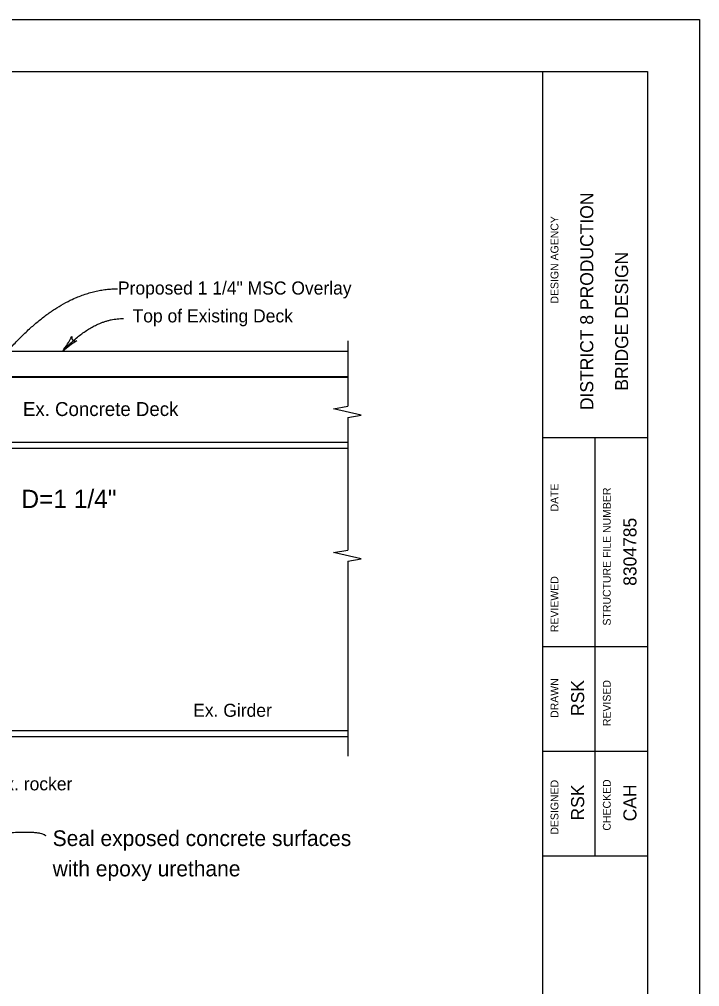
# Model space of a CAD drawing. Extents: x -706 to 14950, y -1867 to 6417.
# Drawn here: x 613.1 to 808.2, y -1354.2 to -1076.7 of the extents above; entities that cross this region are included whole.
import ezdxf

# ---------------------------------------------------------------- set-up
doc = ezdxf.new("R2010")
doc.units = 0
for name, color, linetype in [('Level 1', 7, 'Continuous'), ('Level 42', 7, 'Continuous'), ('Level 43', 7, 'Continuous'), ('Level 44', 7, 'Continuous'), ('Level 47', 7, 'Continuous')]:
    doc.layers.add(name, color=color, linetype=linetype)

msp = doc.modelspace()

# ---------------------------------------------------------------- linework, layer by layer
at = {"layer": 'Level 1'}
for p, q in [((763.17, -1721.66), (763.17, -1091.66)), ((763.17, -1196.66), (793.17, -1196.66)), ((778.17, -1316.66), (778.17, -1196.66)), ((763.17, -1256.66), (793.17, -1256.66)), ((763.17, -1286.66), (793.17, -1286.66)), ((763.17, -1316.66), (793.17, -1316.66))]:
    msp.add_line(p, q, dxfattribs=at)
for points in [[(-211.83, -1076.66), (808.17, -1076.66), (808.17, -1736.66), (-211.83, -1736.66)], [(-151.83, -1091.66), (793.17, -1091.66), (793.17, -1721.66), (-151.83, -1721.66)]]:
    msp.add_lwpolyline(points, close=True, dxfattribs=at)
at = {"layer": 'Level 42'}
for p, q in [((543.75, -1171.85), (707.26, -1171.85)), ((535.62, -1179.35), (707.26, -1179.35))]:
    msp.add_line(p, q, dxfattribs=at)
msp.add_lwpolyline([(543.05, -1179.26), (543.05, -1171.85), (707.26, -1171.85), (707.26, -1179.26)], close=True, dxfattribs=at)
at = {"layer": 'Level 43'}
for p, q in [((536.79, -1198.02), (707.26, -1198.02)), ((536.79, -1199.71), (707.26, -1199.71)), ((531.77, -1280.73), (707.26, -1280.73)), ((531.77, -1282.41), (707.26, -1282.41))]:
    msp.add_line(p, q, dxfattribs=at)
at = {"layer": 'Level 44'}
for p, q in [((629.51, -1168.91), (629.51, -1168.91)), ((707.26, -1168.93), (707.26, -1187.7)), ((703.2, -1188.4), (707.26, -1187.7)), ((711.11, -1190.22), (703.2, -1188.4)), ((707.26, -1190.88), (711.11, -1190.22)), ((707.26, -1190.88), (707.26, -1228.96)), ((703.2, -1229.65), (707.26, -1228.96)), ((711.11, -1231.48), (703.2, -1229.65)), ((707.26, -1232.13), (711.11, -1231.48)), ((707.26, -1232.13), (707.26, -1288.06))]:
    msp.add_line(p, q, dxfattribs=at)
for centre, start, end in [((595.76, -1150.18), 323.9167, 331.6712), ((649.25, -1199.97), 122.437, 130.1914)]:
    msp.add_arc(centre, 36.8, start, end, dxfattribs=at)
msp.add_ellipse((629.27, -1167.8), major_axis=(-0.849, -0.912), ratio=0.873734, start_param=5.258637, end_param=7.300638, dxfattribs=at)
msp.add_open_spline([(597.3, -1313.98), (606.24, -1310.1), (619.74, -1309.68), (620.58, -1310.95)], degree=2, dxfattribs=at)
at = {"layer": 'Level 47'}
for points in [[(608.06, -1173.83), (624.63, -1153.99), (641.2, -1153.99)], [(625.5, -1171.85), (634.21, -1162.5), (642.92, -1162.5)]]:
    msp.add_open_spline(points, degree=2, dxfattribs=at)

# ---------------------------------------------------------------- texts
at = {"layer": 'Level 1'}
for s, height, p in [('  DISTRICT 8 PRODUCTION  ', 3.75, (777.67, -1191.57)), ('DESIGN AGENCY', 2.25, (767.67, -1158.22)), ('      BRIDGE DESIGN      ', 3.75, (787.67, -1191.57)), ('DATE', 2.25, (767.67, -1217.88)), ('STRUCTURE FILE NUMBER', 2.25, (782.67, -1250.62)), ('8304785', 3.75, (790.05, -1239.22)), ('REVIEWED', 2.25, (767.67, -1252.5)), ('DRAWN', 2.25, (767.67, -1277.12)), ('RSK', 3.75, (775.05, -1276.56)), ('REVISED', 2.25, (782.67, -1279.47)), ('DESIGNED', 2.25, (767.67, -1310.62)), ('RSK', 3.75, (775.05, -1306.56)), ('CHECKED', 2.25, (782.67, -1309.47)), ('CAH', 3.75, (790.05, -1306.8))]:
    msp.add_text(s, height=height, rotation=90, dxfattribs=at).set_placement(p)
at = {"layer": 'Level 44'}
for s, height, p in [('Proposed 1 1/4" MSC Overlay', 3.75, (641.35, -1155.63)), ('Top of Existing Deck', 3.75, (645.54, -1163.62)), ('Ex. Concrete Deck', 4, (614.1, -1190.49)), ('D=1 1/4"', 5.25, (613.66, -1216.9)), ('Ex. Girder', 3.75, (662.92, -1276.81)), ('Ex. rocker', 3.75, (605.71, -1297.91)), ('Seal exposed concrete surfaces', 4.5, (622.63, -1313.89)), ('with epoxy urethane', 4.5, (622.63, -1322.6))]:
    msp.add_text(s, height=height, dxfattribs=at).set_placement(p)

doc.saveas('drawing.dxf')
